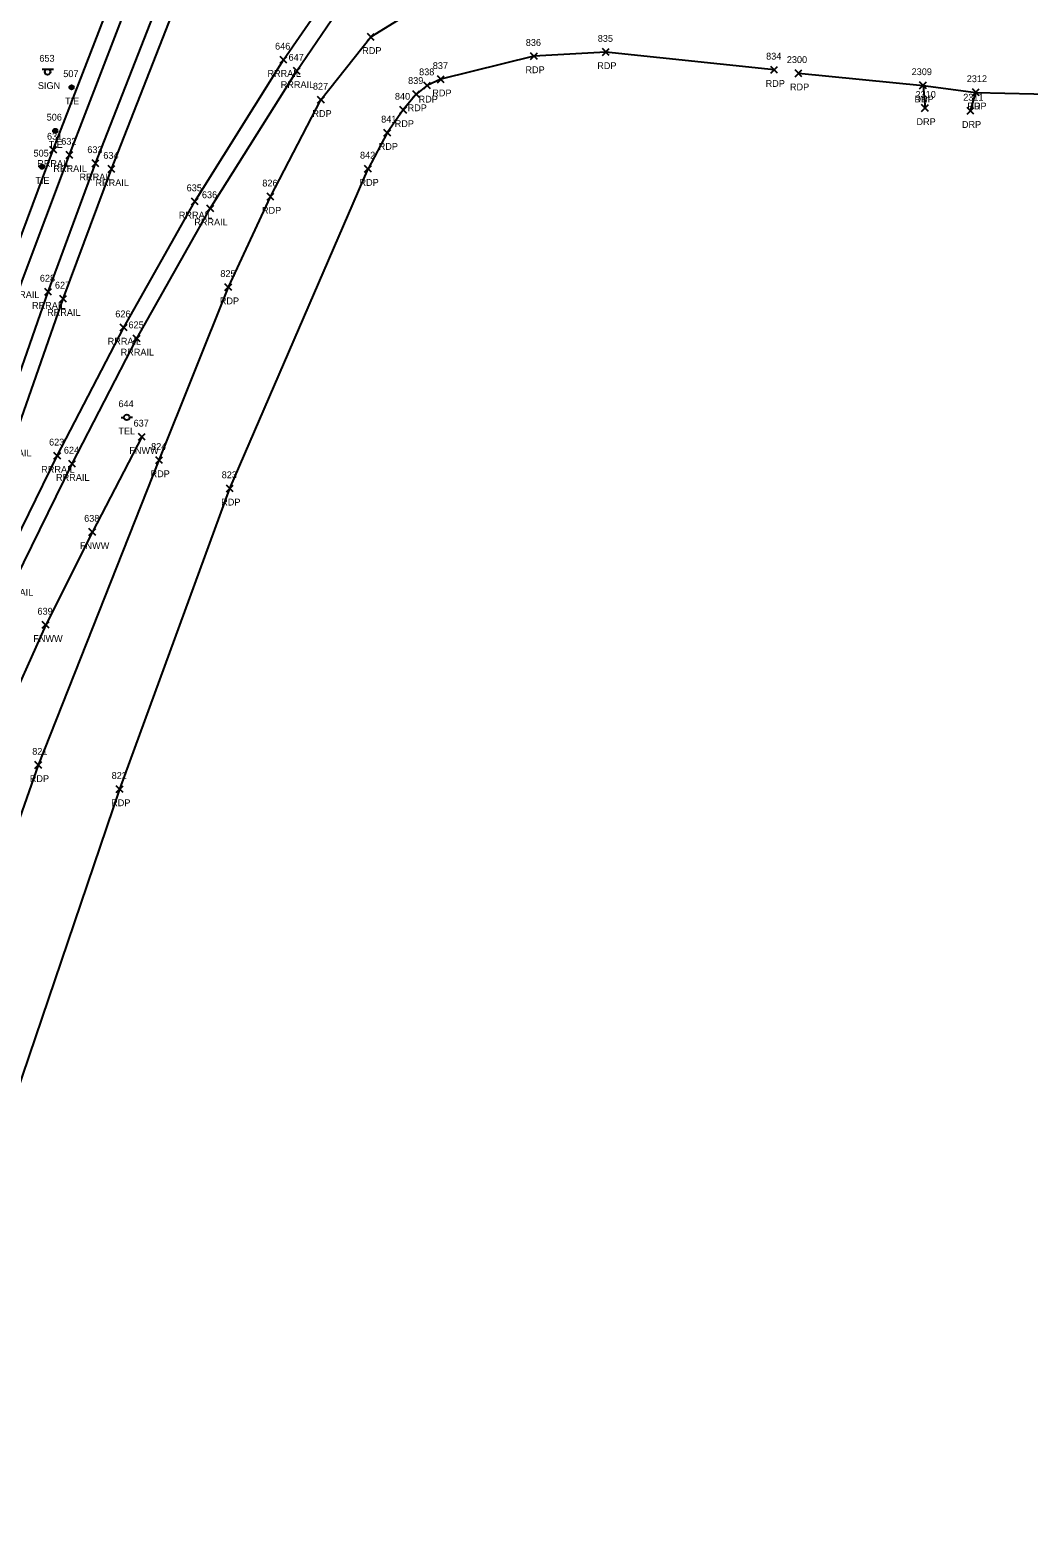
# Model space of a CAD drawing. Extents: x 1767353 to 1772625, y 740790 to 747702.
# Drawn here: x 1770332.7 to 1770625.6, y 741990.7 to 742432.9 of the extents above; entities that cross this region are included whole.
import ezdxf

# ---------------------------------------------------------------- set-up
doc = ezdxf.new("R2010")
doc.units = 0
for name, color, linetype in [('C_A', 7, 'Continuous'), ('C_I', 7, 'Continuous'), ('CBP', 7, 'Continuous'), ('L_A', 7, 'Continuous'), ('L_I', 7, 'Continuous'), ('L_TIC', 7, 'Continuous'), ('LFNC', 7, 'Continuous'), ('P_A', 7, 'Continuous'), ('P_I', 7, 'Continuous'), ('P_TIC', 7, 'Continuous'), ('PET', 7, 'Continuous'), ('R_A', 7, 'Continuous'), ('R_I', 7, 'Continuous'), ('R_TIC', 7, 'Continuous'), ('RDP', 7, 'Continuous'), ('RR', 7, 'Continuous'), ('S_A', 7, 'Continuous'), ('S_I', 7, 'Continuous'), ('SSGN', 7, 'Continuous'), ('U_A', 7, 'Continuous'), ('U_I', 7, 'Continuous'), ('UP', 7, 'Continuous')]:
    doc.layers.add(name, color=color, linetype=linetype)

msp = doc.modelspace()

# ---------------------------------------------------------------- linework, layer by layer
at = {"layer": 'CBP'}
for centre, radius in [((1770344.87, 742416.09), 0.625), ((1770344.87, 742416.09), 0.0833), ((1770340.07, 742403.33), 0.625), ((1770340.07, 742403.33), 0.0833), ((1770336.15, 742392.78), 0.625), ((1770336.15, 742392.78), 0.0833)]:
    msp.add_circle(centre, radius, dxfattribs=at)
at = {"layer": 'L_TIC'}
for points in [[(1770364.47, 742312.6), (1770366.47, 742314.6)], [(1770366.47, 742312.6), (1770364.47, 742314.6)], [(1770349.97, 742284.69), (1770351.97, 742286.69)], [(1770351.97, 742284.69), (1770349.97, 742286.69)], [(1770336.29, 742257.44), (1770338.29, 742259.44)], [(1770338.29, 742257.44), (1770336.29, 742259.44)]]:
    msp.add_lwpolyline(points, dxfattribs=at)
at = {"layer": 'LFNC'}
msp.add_lwpolyline([(1770365.47, 742313.6), (1770350.97, 742285.69), (1770337.29, 742258.44), (1770324.75, 742230.26), (1770311.41, 742190.01)], dxfattribs=at)
at = {"layer": 'P_TIC'}
for points in [[(1770431.62, 742429.87), (1770433.62, 742431.87)], [(1770433.62, 742429.87), (1770431.62, 742431.87)], [(1770479.49, 742424.24), (1770481.49, 742426.24)], [(1770481.49, 742424.24), (1770479.49, 742426.24)], [(1770500.56, 742425.43), (1770502.56, 742427.43)], [(1770502.56, 742425.43), (1770500.56, 742427.43)], [(1770549.93, 742420.22), (1770551.93, 742422.22)], [(1770551.93, 742420.22), (1770549.93, 742422.22)], [(1770557.07, 742419.21), (1770559.07, 742421.21)], [(1770559.07, 742419.21), (1770557.07, 742421.21)], [(1770448.15, 742415.62), (1770450.15, 742417.62)], [(1770450.15, 742415.62), (1770448.15, 742417.62)], [(1770452.17, 742417.45), (1770454.17, 742419.45)], [(1770454.17, 742417.45), (1770452.17, 742419.45)], [(1770593.59, 742415.67), (1770595.59, 742417.67)], [(1770595.59, 742415.67), (1770593.59, 742417.67)], [(1770417.01, 742411.4), (1770419.01, 742413.4)], [(1770419.01, 742411.4), (1770417.01, 742413.4)], [(1770444.93, 742413.08), (1770446.93, 742415.08)], [(1770446.93, 742413.08), (1770444.93, 742415.08)], [(1770609.1, 742413.61), (1770611.1, 742415.61)], [(1770611.1, 742413.61), (1770609.1, 742415.61)], [(1770441.15, 742408.45), (1770443.15, 742410.45)], [(1770443.15, 742408.45), (1770441.15, 742410.45)], [(1770436.46, 742401.75), (1770438.46, 742403.75)], [(1770438.46, 742401.75), (1770436.46, 742403.75)], [(1770430.82, 742391.19), (1770432.82, 742393.19)], [(1770432.82, 742391.19), (1770430.82, 742393.19)], [(1770430.82, 742391.19), (1770432.82, 742393.19)], [(1770432.82, 742391.19), (1770430.82, 742393.19)], [(1770402.22, 742383.01), (1770404.22, 742385.01)], [(1770404.22, 742383.01), (1770402.22, 742385.01)], [(1770389.86, 742356.46), (1770391.86, 742358.46)], [(1770391.86, 742356.46), (1770389.86, 742358.46)], [(1770369.55, 742305.75), (1770371.55, 742307.75)], [(1770371.55, 742305.75), (1770369.55, 742307.75)], [(1770390.26, 742297.45), (1770392.26, 742299.45)], [(1770392.26, 742297.45), (1770390.26, 742299.45)], [(1770334.13, 742216.35), (1770336.13, 742218.35)], [(1770336.13, 742216.35), (1770334.13, 742218.35)], [(1770357.99, 742209.27), (1770359.99, 742211.27)], [(1770359.99, 742209.27), (1770357.99, 742211.27)]]:
    msp.add_lwpolyline(points, dxfattribs=at)
at = {"layer": 'PET'}
for points in [[(1770243.74, 741939.41), (1770255.24, 741954.28), (1770270.92, 742018.28), (1770293.62, 742096.86), (1770309.99, 742145.51), (1770335.13, 742217.35), (1770370.55, 742306.75), (1770390.86, 742357.46), (1770403.22, 742384.01), (1770418.01, 742412.4), (1770432.62, 742430.87), (1770448.87, 742440.9), (1770468.46, 742446.31), (1770490.36, 742448.75), (1770521.27, 742448.09), (1770553.51, 742444.86)], [(1770550.93, 742421.22), (1770501.56, 742426.43), (1770480.49, 742425.24), (1770453.17, 742418.45), (1770449.15, 742416.62), (1770445.93, 742414.08), (1770442.15, 742409.45), (1770437.46, 742402.75), (1770431.82, 742392.19)], [(1770558.07, 742420.21), (1770594.59, 742416.67), (1770610.1, 742414.61), (1770644.11, 742413.83), (1770677.13, 742407.98), (1770724.81, 742402.17), (1770739.48, 742400.39), (1770769.32, 742397.75), (1770789.15, 742394.42), (1770803.42, 742393.52), (1770841.15, 742389.93), (1770854.69, 742389.02), (1770980.6, 742381.86), (1771012.22, 742378.21), (1771016.26, 742375.6), (1771018.35, 742372.34), (1771016.91, 742361.43)], [(1770285.65, 741912.36), (1770284.14, 741916.13), (1770280.49, 741942.89), (1770294.81, 742012.74), (1770319.05, 742092.71), (1770358.99, 742210.27), (1770391.26, 742298.45), (1770431.82, 742392.19)]]:
    msp.add_lwpolyline(points, dxfattribs=at)
at = {"layer": 'R_TIC'}
for points in [[(1770406.02, 742423.16), (1770408.02, 742425.16)], [(1770408.02, 742423.16), (1770406.02, 742425.16)], [(1770409.92, 742419.89), (1770411.92, 742421.89)], [(1770411.92, 742419.89), (1770409.92, 742421.89)], [(1770593.59, 742415.67), (1770595.59, 742417.67)], [(1770595.59, 742415.67), (1770593.59, 742417.67)], [(1770609.1, 742413.61), (1770611.1, 742415.61)], [(1770611.1, 742413.61), (1770609.1, 742415.61)], [(1770594.17, 742409.01), (1770596.17, 742411.01)], [(1770596.17, 742409.01), (1770594.17, 742411.01)], [(1770607.51, 742408.19), (1770609.51, 742410.19)], [(1770609.51, 742408.19), (1770607.51, 742410.19)], [(1770338.5, 742396.74), (1770340.5, 742398.74)], [(1770340.5, 742396.74), (1770338.5, 742398.74)], [(1770343.25, 742395.26), (1770345.25, 742397.26)], [(1770345.25, 742395.26), (1770343.25, 742397.26)], [(1770350.9, 742392.8), (1770352.9, 742394.8)], [(1770352.9, 742392.8), (1770350.9, 742394.8)], [(1770355.59, 742391.13), (1770357.59, 742393.13)], [(1770357.59, 742391.13), (1770355.59, 742393.13)], [(1770380.03, 742381.61), (1770382.03, 742383.61)], [(1770382.03, 742381.61), (1770380.03, 742383.61)], [(1770384.56, 742379.58), (1770386.56, 742381.58)], [(1770386.56, 742379.58), (1770384.56, 742381.58)], [(1770336.98, 742355.11), (1770338.98, 742357.11)], [(1770338.98, 742355.11), (1770336.98, 742357.11)], [(1770341.4, 742353.07), (1770343.4, 742355.07)], [(1770343.4, 742353.07), (1770341.4, 742355.07)], [(1770359.15, 742344.64), (1770361.15, 742346.64)], [(1770361.15, 742344.64), (1770359.15, 742346.64)], [(1770362.97, 742341.43), (1770364.97, 742343.43)], [(1770364.97, 742341.43), (1770362.97, 742343.43)], [(1770339.68, 742307.04), (1770341.68, 742309.04)], [(1770341.68, 742307.04), (1770339.68, 742309.04)], [(1770344.02, 742304.68), (1770346.02, 742306.68)], [(1770346.02, 742304.68), (1770344.02, 742306.68)]]:
    msp.add_lwpolyline(points, dxfattribs=at)
at = {"layer": 'RDP'}
for points in [[(1770594.59, 742416.67), (1770595.17, 742410.01)], [(1770608.51, 742409.19), (1770610.1, 742414.61)]]:
    msp.add_lwpolyline(points, dxfattribs=at)
at = {"layer": 'RR'}
for points in [[(1770221.78, 741982.04), (1770226.9, 742005.14), (1770231.58, 742026.58), (1770238.97, 742057.62), (1770247.46, 742091.31), (1770255.17, 742120.86), (1770262.38, 742147.12), (1770270.79, 742177.04), (1770278.58, 742203.25), (1770285.57, 742226.22), (1770292.18, 742247.12), (1770303.7, 742282.6), (1770315.3, 742316.87), (1770330.35, 742359.31), (1770344.25, 742396.26), (1770362.68, 742444.08), (1770381.25, 742488.48), (1770399.89, 742531.75), (1770427.72, 742593.02), (1770459.92, 742661.06), (1770775.2, 743314.07), (1770996.39, 743772.66), (1771192.02, 744177.67), (1771329.71, 744462.72)], [(1770217.88, 741982.89), (1770224.63, 742006.05), (1770231.58, 742026.58), (1770242.49, 742057.3), (1770253.86, 742089.03), (1770263.22, 742117.76), (1770271, 742143.83), (1770279.57, 742174.49), (1770286.79, 742199.43), (1770293.9, 742223.08), (1770300.84, 742244.95), (1770311.67, 742279.15), (1770323.34, 742314.32), (1770337.98, 742356.11), (1770351.9, 742393.8), (1770370.52, 742441.44), (1770388.76, 742485.07), (1770407.79, 742528.71), (1770435.51, 742589.24), (1770468.44, 742657.89), (1770783.17, 743309.95), (1771004.51, 743768.91), (1771200.35, 744174.24), (1771337.45, 744458.43)], [(1770217.02, 741983.21), (1770222.11, 742006.18), (1770226.99, 742028.12), (1770234.33, 742059.23), (1770242.65, 742092.71), (1770250.33, 742121.94), (1770257.59, 742148.49), (1770265.95, 742178.19), (1770273.77, 742204.67), (1770280.68, 742227.53), (1770287.46, 742248.27), (1770299.11, 742284.6), (1770310.51, 742317.94), (1770325.96, 742361.53), (1770339.5, 742397.74), (1770358.03, 742445.88), (1770376.8, 742490.97), (1770395.2, 742533.35), (1770423.54, 742595.68), (1770455.2, 742662.62), (1770770.92, 743316.68), (1770991.9, 743774.87)], [(1770222.72, 741981.76), (1770229.32, 742004.36), (1770235.77, 742023.83), (1770247.09, 742055.41), (1770258.52, 742087.39), (1770268.11, 742116.55), (1770275.73, 742142.21), (1770291.55, 742198.01), (1770296.52, 742214.73), (1770305.48, 742243.41), (1770316.35, 742277.3), (1770328.03, 742312.86), (1770342.4, 742354.07), (1770356.59, 742392.13), (1770375.3, 742439.98), (1770392.87, 742482.18), (1770412.29, 742526.82), (1770439.88, 742586.94), (1770472.88, 742655.84), (1770787.34, 743307.49), (1771008.99, 743766.96)], [(1770271.52, 742143.69), (1770280.69, 742174.18), (1770289.74, 742198.6), (1770296.52, 742214.73), (1770308.93, 742241.95), (1770324.06, 742274.04), (1770340.68, 742308.04), (1770360.15, 742345.64), (1770381.03, 742382.61), (1770407.02, 742424.16), (1770425.18, 742450.58), (1770450.26, 742483.52), (1770473.18, 742510.79), (1770518.15, 742562.81), (1770572.7, 742627.85), (1770598.36, 742661.22), (1770630.52, 742706.14), (1770655.11, 742743.9), (1770674.5, 742775.55), (1770683.79, 742791.45), (1770706.15, 742833.16), (1770731.07, 742883.64), (1770775.22, 742979.87)], [(1770275.73, 742142.21), (1770285.7, 742173.47), (1770294.36, 742196.77), (1770301.28, 742213.26), (1770313.54, 742240.29), (1770328.52, 742271.98), (1770345.02, 742305.68), (1770363.97, 742342.43), (1770385.56, 742380.58), (1770410.92, 742420.89), (1770428.56, 742446.86), (1770454.89, 742481.33), (1770476.7, 742507.31), (1770522.14, 742559.86), (1770576.25, 742624.32), (1770602.26, 742658.04), (1770634.11, 742702.9), (1770659.93, 742742.21), (1770678.83, 742773.23), (1770687.73, 742788.35), (1770710.35, 742830.29), (1770735.06, 742880.72), (1770779.65, 742978.02)]]:
    msp.add_lwpolyline(points, dxfattribs=at)
at = {"layer": 'SSGN'}
for p, q in [((1770336.2, 742421.45), (1770339.53, 742421.45)), ((1770337.85, 742420.62), (1770337.85, 742420.62))]:
    msp.add_line(p, q, dxfattribs=at)
msp.add_circle((1770337.85, 742420.62), 0.833, dxfattribs=at)
at = {"layer": 'UP'}
for p, q in [((1770359.37, 742319.29), (1770360.2, 742319.29)), ((1770361.03, 742319.3), (1770361.03, 742319.3)), ((1770362.7, 742319.3), (1770361.86, 742319.3)), ((1770361.86, 742319.3), (1770361.86, 742319.3)), ((1770362.7, 742319.3), (1770362.7, 742319.3))]:
    msp.add_line(p, q, dxfattribs=at)
msp.add_circle((1770361.03, 742319.3), 0.833, dxfattribs=at)

# ---------------------------------------------------------------- texts
at = {"layer": 'C_A'}
for p in [(1770342.95, 742411.09), (1770338.14, 742398.33), (1770334.23, 742387.78)]:
    msp.add_text('TIE', height=2, dxfattribs=at).set_placement(p)
at = {"layer": 'C_I'}
for s, p in [('507', (1770342.43, 742419.09)), ('506', (1770337.57, 742406.33)), ('505', (1770333.71, 742395.78))]:
    msp.add_text(s, height=2, dxfattribs=at).set_placement(p)
at = {"layer": 'L_A'}
for p in [(1770361.81, 742308.6), (1770347.32, 742280.69), (1770333.64, 742253.44)]:
    msp.add_text('FNWW', height=2, dxfattribs=at).set_placement(p)
at = {"layer": 'L_I'}
for s, p in [('637', (1770363.06, 742316.6)), ('638', (1770348.56, 742288.69)), ('639', (1770334.87, 742261.44))]:
    msp.add_text(s, height=2, dxfattribs=at).set_placement(p)
at = {"layer": 'P_A'}
for p in [(1770430.11, 742425.87), (1770477.98, 742420.24), (1770499.04, 742421.43), (1770548.42, 742416.22), (1770555.55, 742415.21), (1770446.64, 742411.62), (1770450.66, 742413.45), (1770592.08, 742411.67), (1770415.5, 742407.4), (1770443.42, 742409.08), (1770607.59, 742409.61), (1770439.64, 742404.45), (1770434.95, 742397.75), (1770429.31, 742387.19), (1770429.31, 742387.19), (1770400.71, 742379.01), (1770388.35, 742352.46), (1770368.04, 742301.75), (1770388.75, 742293.45), (1770332.62, 742212.35), (1770356.48, 742205.27)]:
    msp.add_text('RDP', height=2, dxfattribs=at).set_placement(p)
at = {"layer": 'P_I'}
for s, p in [('836', (1770478.08, 742428.24)), ('835', (1770499.19, 742429.43)), ('834', (1770548.57, 742424.22)), ('838', (1770446.79, 742419.62)), ('837', (1770450.81, 742421.45)), ('2300', (1770554.64, 742423.21)), ('2309', (1770591.25, 742419.67)), ('827', (1770415.65, 742415.4)), ('839', (1770443.56, 742417.08)), ('2312', (1770607.41, 742417.61)), ('840', (1770439.7, 742412.45)), ('841', (1770435.67, 742405.75)), ('842', (1770429.46, 742395.19)), ('842', (1770429.46, 742395.19)), ('826', (1770400.81, 742387.01)), ('825', (1770388.5, 742360.46)), ('824', (1770368.19, 742309.75)), ('823', (1770388.9, 742301.45)), ('821', (1770333.33, 742220.35)), ('822', (1770356.63, 742213.27))]:
    msp.add_text(s, height=2, dxfattribs=at).set_placement(p)
at = {"layer": 'R_A'}
for s, p in [('RRRAIL', (1770402.31, 742419.16)), ('RRRAIL', (1770406.21, 742415.89)), ('DRP', (1770592.08, 742411.67)), ('DRP', (1770607.59, 742409.61)), ('DRP', (1770592.66, 742405.01)), ('DRP', (1770605.99, 742404.19)), ('RRRAIL', (1770334.79, 742392.74)), ('RRRAIL', (1770339.54, 742391.26)), ('RRRAIL', (1770347.19, 742388.8)), ('RRRAIL', (1770351.88, 742387.13)), ('RRRAIL', (1770376.32, 742377.61)), ('RRRAIL', (1770380.86, 742375.58)), ('RRRAIL', (1770325.64, 742354.31)), ('RRRAIL', (1770333.27, 742351.11)), ('RRRAIL', (1770337.69, 742349.07)), ('RRRAIL', (1770355.45, 742340.64)), ('RRRAIL', (1770359.26, 742337.43)), ('RRRAIL', (1770323.32, 742307.86)), ('RRRAIL', (1770335.97, 742303.04)), ('RRRAIL', (1770340.31, 742300.68)), ('RRRAIL', (1770323.82, 742266.98))]:
    msp.add_text(s, height=2, dxfattribs=at).set_placement(p)
at = {"layer": 'R_I'}
for s, p in [('646', (1770404.55, 742427.16)), ('647', (1770408.51, 742423.89)), ('2309', (1770591.25, 742419.67)), ('2312', (1770607.41, 742417.61)), ('2310', (1770592.39, 742413.01)), ('2311', (1770606.38, 742412.19)), ('631', (1770337.66, 742400.74)), ('632', (1770341.84, 742399.26)), ('633', (1770349.49, 742396.8)), ('634', (1770354.18, 742395.13)), ('635', (1770378.62, 742385.61)), ('636', (1770383.1, 742383.58)), ('628', (1770335.57, 742359.11)), ('627', (1770339.99, 742357.07)), ('626', (1770357.69, 742348.64)), ('625', (1770361.56, 742345.43)), ('623', (1770338.27, 742311.04)), ('624', (1770342.61, 742308.68))]:
    msp.add_text(s, height=2, dxfattribs=at).set_placement(p)
at = {"layer": 'S_A'}
msp.add_text('SIGN', height=2, dxfattribs=at).set_placement((1770334.99, 742415.6))
at = {"layer": 'S_I'}
msp.add_text('653', height=2, dxfattribs=at).set_placement((1770335.42, 742423.6))
at = {"layer": 'U_A'}
msp.add_text('TEL', height=2, dxfattribs=at).set_placement((1770358.59, 742314.3))
at = {"layer": 'U_I'}
msp.add_text('644', height=2, dxfattribs=at).set_placement((1770358.62, 742322.3))

doc.saveas('drawing.dxf')
